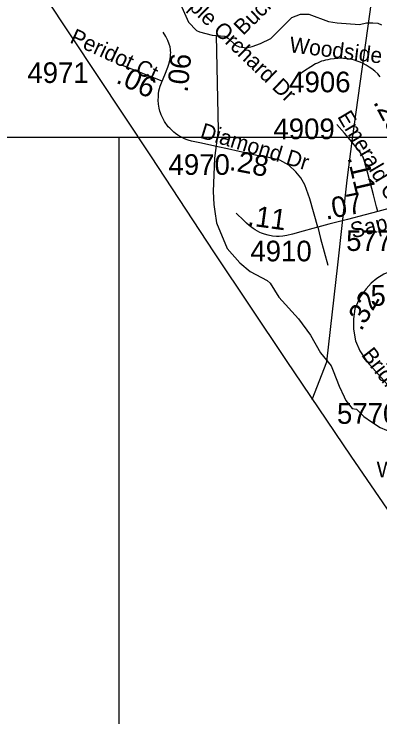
# Model space of a CAD drawing. Extents: x 1383679 to 1536984, y 460658 to 651027.
# Drawn here: x 1436839 to 1439057, y 473807 to 478063 of the extents above; entities that cross this region are included whole.
import ezdxf

# ---------------------------------------------------------------- set-up
doc = ezdxf.new("R2010")
doc.units = 0
for name, color, linetype in [('Exist Boundary Political StateLine', 7, 'Continuous'), ('Exist Hydrographic Misc Water Feature', 7, 'Continuous'), ('Exist Road Non-System Type 51', 7, 'Continuous'), ('Exist Road Non-System Type 51 Label', 7, 'Continuous'), ('Exist Road Secondary Mileage Hundredths English Label', 7, 'Continuous'), ('Exist Road Secondary Type 51 Attributed', 7, 'Continuous'), ('Exist Road Secondary Type 51 Label', 7, 'Continuous'), ('Exist Road Secondary Type 51 Number Label', 7, 'Continuous'), ('Exist Utilities Electrical Transmission Line', 7, 'Continuous'), ('Map Preparation Inset Cut Line', 7, 'Continuous')]:
    doc.layers.add(name, color=color, linetype=linetype)

msp = doc.modelspace()

# ---------------------------------------------------------------- linework, layer by layer
at = {"layer": 'Exist Boundary Political StateLine'}
msp.add_lwpolyline([(1443385.7, 468860.6), (1442857.3, 469616.4), (1442270.4, 470457.6), (1441736.3, 471231.7), (1441054.2, 472226.4), (1440397.5, 473190.9), (1439900.4, 473912.2), (1439582.6, 474364.2), (1438883, 475385.3), (1438491.3, 475964.4), (1438054.4, 476617.4), (1437668.2, 477203.2), (1436861, 478419.8), (1436471, 479017.8), (1436036, 479664.8), (1435409.6, 480533.7), (1434942.5, 481173.4), (1434317.4, 482010.1), (1433106.8, 483665.1)], dxfattribs=at)
at = {"layer": 'Exist Hydrographic Misc Water Feature'}
for points in [[(1436990.3, 478260.6), (1437041, 478260.2), (1437166.8, 478246.2), (1437299.1, 478261.6), (1437353.3, 478270.3), (1437521.7, 478286.7), (1437571.7, 478285.6), (1437593.7, 478281.9), (1437664.9, 478237.8), (1437720.4, 478212.9), (1437754.4, 478210.6), (1437792.3, 478209.8), (1437810.2, 478202.9), (1437856.4, 478104.3), (1437896.6, 478013.2), (1437945.7, 477962.2), (1437963.4, 477954.4), (1438039.2, 477934.8), (1438063.1, 477931.9)], [(1438063.1, 477931.9), (1438117.1, 477929.2), (1438136.8, 477916.5), (1438181.9, 477873.7), (1438203.7, 477863.4), (1438247.7, 477858.5), (1438281.9, 477866), (1438332.3, 477884.6), (1438394.8, 477915.4), (1438523.4, 478041.6), (1438575.8, 478061.9), (1438625.8, 478060.9), (1438745.4, 478016.8), (1438797.8, 478008.7), (1438932.3, 477999.7)], [(1438932.3, 477999.7), (1438974.4, 478008.8), (1439014.4, 478009.6), (1439044.4, 478007.4), (1439066.3, 477997.1)], [(1438063.1, 477931.9), (1438071.6, 477550.2), (1438075.9, 477359.7), (1438054.6, 477190.2), (1438046.7, 476987.7), (1438049.1, 476909.7), (1438056.3, 476867.7), (1438066.9, 476797.8), (1438129.9, 476642.2), (1438208.3, 476556.9), (1438269.2, 476503.2), (1438372.3, 476449.4), (1438392, 476433.4), (1438444.4, 476347.9), (1438563.8, 476217.4), (1438636, 476118.3), (1438695.9, 476011.3), (1438760.5, 475932), (1438773.8, 475903), (1438810.2, 475810.4), (1438839.1, 475744.2), (1438850.7, 475723.4), (1438887.7, 475673.4)], [(1438887.7, 475673.4), (1438913.7, 475670.4), (1438958.8, 475626), (1439006.3, 475593.1), (1439057.7, 475560), (1439097.5, 475543.7), (1439141.2, 475530.4), (1439211.1, 475520.9)]]:
    msp.add_lwpolyline(points, dxfattribs=at)
at = {"layer": 'Exist Road Non-System Type 51'}
msp.add_lwpolyline([(1438680, 476771.6), (1438697.3, 476702.9), (1438739.9, 476542.4)], dxfattribs=at)
at = {"layer": 'Exist Road Secondary Type 51 Attributed'}
for points in [[(1437737.1, 477656.8), (1437752.5, 477694.9), (1437770.9, 477741.4), (1437777.2, 477758.9), (1437782, 477773.9), (1437785.3, 477790.5), (1437787.4, 477804.6), (1437787.9, 477817.3), (1437788.4, 477829.9), (1437787.9, 477839), (1437787.2, 477847.8), (1437784.2, 477864), (1437779.7, 477880.6), (1437771.9, 477901.7), (1437759.1, 477926.2), (1437743.6, 477952)], [(1439058.5, 477682.8), (1439043.1, 477700.6), (1439025.5, 477716.1), (1439007.8, 477730), (1438991.3, 477741.4), (1438972.6, 477753), (1438954.9, 477763.1), (1438936.1, 477770.5), (1438919.3, 477776.9), (1438901.7, 477782.5), (1438886.6, 477786.6), (1438872.2, 477790), (1438859.1, 477791.7), (1438836.8, 477793.2), (1438820.4, 477794.5), (1438800.8, 477793.5), (1438780.2, 477792), (1438756, 477789.2), (1438740.5, 477786.3), (1438726.1, 477783.4), (1438714.1, 477779.6), (1438703.5, 477776.5), (1438689.8, 477771.4), (1438677.3, 477765.8), (1438666.5, 477760.3), (1438638.1, 477743.4), (1438598.8, 477719.1), (1438565.5, 477694.4)], [(1437737.1, 477656.8), (1437553.2, 477728.7), (1437495.8, 477751.5)], [(1438680, 476771.6), (1438632.4, 476943.8), (1438601.3, 477027.7), (1438577.1, 477071.3), (1438546, 477106.5), (1438504.5, 477148.4), (1438449.2, 477178.6), (1438354.1, 477200.4), (1438343.4, 477202.6), (1438310.4, 477206.7), (1438257.3, 477218.3), (1438204, 477229.9), (1438132.8, 477245.8), (1438075, 477258), (1438055, 477262.2), (1437974.3, 477280.3), (1437913.6, 477293.8), (1437894.1, 477298.8), (1437881.9, 477303.1), (1437867.3, 477309.8), (1437857.6, 477314.6), (1437849, 477319.3), (1437832.6, 477328.5), (1437817.5, 477339.1), (1437806.9, 477348.2), (1437792.8, 477360.7), (1437782.4, 477371.1), (1437773.9, 477380.4), (1437765.1, 477392.1), (1437758.5, 477400.6), (1437750.6, 477412.6), (1437744, 477424), (1437735.7, 477440.4), (1437730.3, 477452.1), (1437726.1, 477463.9), (1437722.8, 477475.1), (1437718.8, 477493.6), (1437716.8, 477505.1), (1437714.7, 477517.5), (1437713, 477540.6), (1437713.4, 477561.4), (1437714.9, 477579.6), (1437717.4, 477598.5), (1437720.1, 477612), (1437724.9, 477626.6), (1437737.1, 477656.8)], [(1439043.3, 476866.2), (1439035.8, 476895), (1439016.9, 476967.5), (1438996.7, 477043.8), (1438990.9, 477066), (1438980.5, 477106.1), (1438965.5, 477163.9), (1438959.5, 477183), (1438954.5, 477197), (1438951.4, 477202.6), (1438947, 477210.6), (1438935, 477228.6), (1438918.8, 477248.6), (1438885.5, 477288.1), (1438841.5, 477341.2), (1438796.3, 477394.5)], [(1439455.7, 477166.1), (1439451.7, 477149.5), (1439440.9, 477116.2), (1439419.7, 477066), (1439414.5, 477055.2), (1439354.7, 476980.4), (1439332.4, 476962.8), (1439310.9, 476948.3), (1439286.2, 476934.8), (1439229, 476915.2), (1439166, 476898.7), (1439088.7, 476878.3), (1439043.3, 476866.2)], [(1439043.3, 476866.2), (1438967.4, 476846), (1438860.6, 476818.9), (1438747.6, 476789.7), (1438680, 476771.6)], [(1438680, 476771.6), (1438649.7, 476763.5), (1438591.9, 476748), (1438525.8, 476730.2), (1438491.9, 476721.1), (1438468.7, 476716.9), (1438446.5, 476715.2), (1438429.1, 476715.5), (1438404.7, 476718.2), (1438378.8, 476723.1), (1438357.5, 476728.9), (1438339.1, 476736.3), (1438329.3, 476740.5), (1438301, 476756), (1438288, 476764.4), (1438264.3, 476783), (1438248.6, 476796.6), (1438231.5, 476813.3), (1438185.5, 476857.9)], [(1439633.9, 476388.9), (1439521.4, 476453.5), (1439431.9, 476501.7), (1439383.6, 476522.2), (1439333.1, 476536.1), (1439289, 476541.5), (1439243.9, 476540.4), (1439200.9, 476531.8), (1439134.3, 476509.3), (1439079.5, 476486.7), (1439038.6, 476460.9), (1439003.2, 476432.9), (1438973.1, 476398.5), (1438937.6, 476351.2), (1438905, 476277), (1438896, 476218.2), (1438896, 476155.6), (1438908, 476083.3), (1438934.3, 476023.9), (1438979.1, 475956.2), (1439146.8, 475769.2), (1439209, 475705.6), (1439249.9, 475655.8), (1439301.4, 475586.5)]]:
    msp.add_lwpolyline(points, dxfattribs=at)
at = {"layer": 'Exist Utilities Electrical Transmission Line'}
msp.add_lwpolyline([(1438645.4, 475729.3), (1438734.5, 475957.3), (1438802.3, 476543.9), (1438858.7, 477056.6), (1438889.8, 477309.9), (1439051.8, 478469.4)], dxfattribs=at)
at = {"layer": 'Map Preparation Inset Cut Line'}
for points in [[(1446195.4, 477316), (1383679.3, 477316), (1383679.3, 520758.2), (1458567.8, 520758.2), (1458567.8, 493672.2), (1446195.4, 493672.2), (1446195.4, 477316)], [(1437474.3, 477316), (1437474.3, 461213.3), (1475802.8, 461213.3), (1475802.8, 477316), (1437474.3, 477316)]]:
    msp.add_lwpolyline(points, dxfattribs=at)

# ---------------------------------------------------------------- texts
at = {"layer": 'Exist Road Non-System Type 51 Label'}
for s, rotation, p in [('Buck Creek Ct', 44.6317, (1438227.6, 477929)), ('Apple Orchard Dr', 316.0831, (1437781.7, 478207.6))]:
    msp.add_text(s, height=95, rotation=rotation, dxfattribs=at).set_placement(p)
at = {"layer": 'Exist Road Secondary Mileage Hundredths English Label'}
for s, rotation, p in [('.06', 84.2922, (1437890.7, 477585.3)), ('.06', 334.6435, (1437450.7, 477649.2)), ('.23', 297.8977, (1439014, 477529)), ('.28', 349.2515, (1438139, 477119.2)), ('.11', 283.0888, (1438859.5, 477193.1)), ('.07', 11.3151, (1438730.3, 476816.7)), ('.11', 352.1855, (1438249.7, 476784.2)), ('.32', 60.3566, (1438943.9, 476138.1))]:
    msp.add_text(s, height=125, rotation=rotation, dxfattribs=at).set_placement(p)
at = {"layer": 'Exist Road Secondary Type 51 Label'}
for s, rotation, p in [('Peridot Ct', 335.1153, (1437171.4, 477892.1)), ('Woodside Falls Rd', 352.9617, (1438504.4, 477831.9)), ('Emerald Ct', 300.6978, (1438796, 477442.3)), ('Diamond Dr', 342.9108, (1437961.3, 477314.6)), ('Sapphire Ln', 14.031, (1438891, 476703.3)), ('Bridle', 307.7606, (1438940.5, 475997.5)), ('Windfall', 0.1222, (1439036.9, 475257.1))]:
    msp.add_text(s, height=95, rotation=rotation, dxfattribs=at).set_placement(p)
at = {"layer": 'Exist Road Secondary Type 51 Number Label'}
for s, p in [('4971', (1436919.5, 477645.2)), ('4906', (1438506.7, 477588.9)), ('4909', (1438411, 477305)), ('4970', (1437775.2, 477089)), ('5772', (1438852, 476628.3)), ('4910', (1438271.4, 476565.3)), ('5769', (1438999.5, 476296.3)), ('5770', (1438796.4, 475581.6))]:
    msp.add_text(s, height=125, dxfattribs=at).set_placement(p)

doc.saveas('drawing.dxf')
